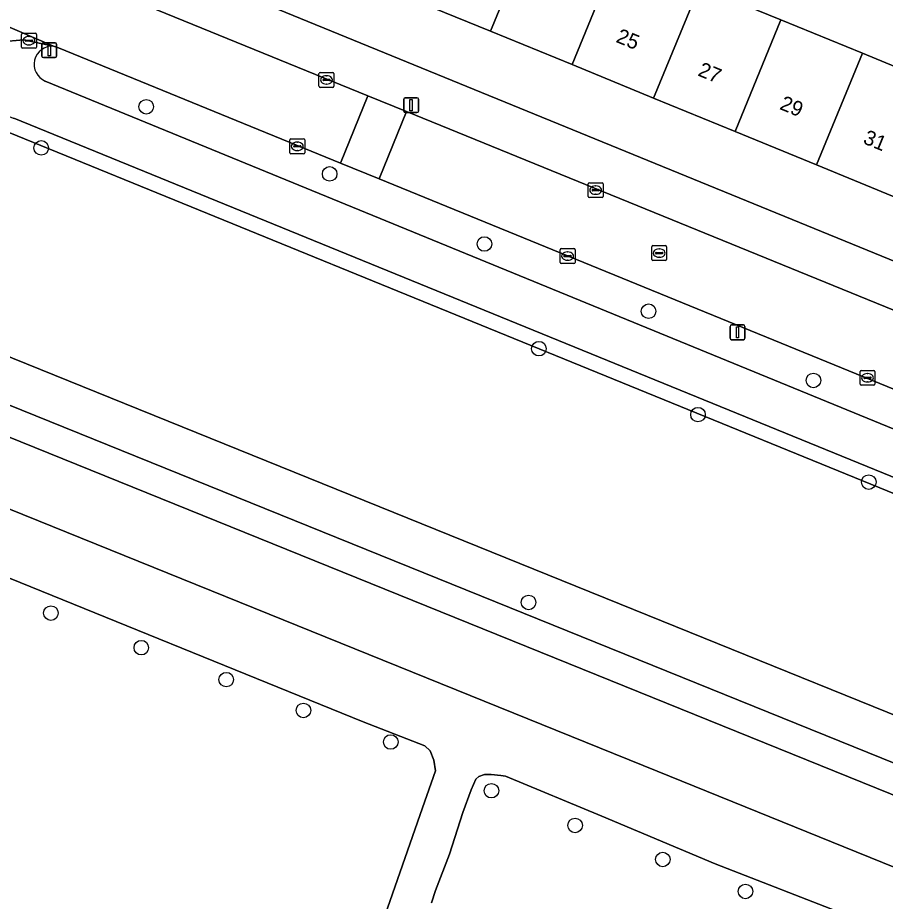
# Model space of a CAD drawing. Extents: x 163008 to 163854, y 382777 to 383982.
# Drawn here: x 163552.6 to 163610.9, y 383061.9 to 383121.3 of the extents above; entities that cross this region are included whole.
import ezdxf

# ---------------------------------------------------------------- set-up
doc = ezdxf.new("R2010")
doc.units = 0
for name, color, linetype in [('IMGEO_Berm_groen', 7, 'Continuous'), ('IMGEO_Boom', 7, 'Continuous'), ('IMGEO_Erf', 7, 'Continuous'), ('IMGEO_Groenvoorziening', 7, 'Continuous'), ('IMGEO_Hek', 7, 'Continuous'), ('IMGEO_Kolk', 7, 'Continuous'), ('IMGEO_Lichtmast', 7, 'Continuous'), ('IMGEO_Pand', 7, 'Continuous'), ('IMGEO_Pand_nummerreeks', 7, 'Continuous'), ('IMGEO_Parkeervlak_open', 7, 'Continuous'), ('IMGEO_Rijbaan_lokaal_open', 7, 'Continuous'), ('IMGEO_Rioolput', 7, 'Continuous'), ('IMGEO_Voetpad_gesloten', 7, 'Continuous'), ('IMGEO_Voetpad_open', 7, 'Continuous')]:
    doc.layers.add(name, color=color, linetype=linetype)

msp = doc.modelspace()

# ---------------------------------------------------------------- linework, layer by layer
at = {"layer": 'IMGEO_Berm_groen'}
for points in [[(163633.015, 383087.498), (163631.359, 383088.175), (163576.844, 383110.459), (163574.252, 383111.519), (163555.314, 383119.26), (163554.966, 383119.373)], [(163554.417, 383117.031), (163686.887, 383062.727), (163714.179, 383051.656), (163715.856, 383050.902), (163716.385, 383050.818), (163716.76, 383053.267), (163697.913, 383060.965), (163695.331, 383062.02), (163685.312, 383066.121), (163633.015, 383087.498)]]:
    msp.add_lwpolyline(points, dxfattribs=at)
msp.add_arc((163554.875, 383118.159), 1.217, 85.72672, 247.88771, dxfattribs=at)
at = {"layer": 'IMGEO_Boom'}
for centre in [(163561.196, 383115.303), (163554.141, 383112.541), (163573.523, 383110.796), (163583.92, 383106.088), (163594.951, 383101.57), (163587.584, 383099.053), (163606.03, 383096.921), (163598.27, 383094.624), (163609.743, 383090.094), (163586.888, 383082.01), (163554.791, 383081.29), (163560.866, 383078.968), (163566.573, 383076.823), (163571.758, 383074.753), (163577.63, 383072.633), (163584.393, 383069.36), (163590.011, 383067.025), (163595.908, 383064.74), (163601.462, 383062.595)]:
    msp.add_circle(centre, 0.489, dxfattribs=at)
at = {"layer": 'IMGEO_Erf'}
for points in [[(163611.721, 383109.153), (163606.243, 383111.398), (163600.766, 383113.643), (163595.287, 383115.889), (163589.811, 383118.134), (163584.332, 383120.38), (163578.855, 383122.625), (163573.377, 383124.871), (163567.9, 383127.116), (163562.422, 383129.362), (163556.757, 383131.684), (163555.276, 383128.633), (163555.2, 383128.339), (163555.351, 383127.886), (163648.196, 383089.907)], [(163598.363, 383123.391), (163603.841, 383121.145), (163609.319, 383118.9), (163614.796, 383116.655)]]:
    msp.add_lwpolyline(points, dxfattribs=at)
at = {"layer": 'IMGEO_Groenvoorziening'}
for points in [[(163716.496, 383040.091), (163717.253, 383045.653), (163715.928, 383047.135), (163714.893, 383048.292), (163712.787, 383049.042), (163686.049, 383059.953), (163684.533, 383060.571), (163683.641, 383060.935), (163682.71, 383061.315), (163552.303, 383114.53)], [(163548.402, 383113.844), (163537.893, 383104.199), (163535.444, 383101.951), (163672.395, 383046.546)], [(163715.519, 383040.306), (163716.256, 383044.834), (163714.021, 383047.565), (163682.332, 383060.389), (163551.925, 383113.604)], [(163551.925, 383113.604), (163682.332, 383060.389), (163714.021, 383047.565), (163716.256, 383044.834), (163715.519, 383040.306)], [(163549.078, 383113.107), (163538.918, 383103.782), (163673.52, 383049.327)], [(163673.52, 383049.327), (163538.918, 383103.782)], [(163535.444, 383101.951), (163533.814, 383100.455), (163671.636, 383044.697), (163673.119, 383044.03), (163675.855, 383042.527), (163676.469, 383042.1), (163678.419, 383040.746), (163680.783, 383038.707), (163682.026, 383037.276), (163683.551, 383038.568), (163682.233, 383040.085)], [(163672.395, 383046.546), (163535.444, 383101.951)], [(163671.636, 383044.697), (163533.814, 383100.455)], [(163547.123, 383090.252), (163595.525, 383070.679), (163613.979, 383063.189)], [(163608.409, 383060.95), (163599.416, 383064.447), (163591.815, 383067.641), (163585.343, 383070.338), (163585.029, 383070.374), (163584.368, 383070.447), (163583.933, 383070.447), (163583.54, 383070.317), (163583.353, 383070.144), (163583.039, 383069.427), (163582.464, 383067.89), (163581.572, 383065.105), (163580.642, 383062.658), (163580.364, 383061.824)]]:
    msp.add_lwpolyline(points, dxfattribs=at)
msp.add_lwpolyline([(163547.02, 383081.384), (163546.673, 383080.294), (163540.33, 383061.689), (163539.081, 383058.231), (163572.325, 383046.79), (163572.711, 383047.998), (163579.758, 383068.217), (163580.638, 383070.701), (163580.512, 383071.408), (163580.28, 383072.028), (163579.921, 383072.377), (163575.785, 383073.992), (163549.831, 383084.522), (163549.324, 383084.673), (163548.823, 383084.551), (163548.394, 383084.316), (163548.147, 383084.045), (163547.849, 383083.514)], close=True, dxfattribs=at)
at = {"layer": 'IMGEO_Hek'}
msp.add_lwpolyline([(163533.814, 383100.455), (163671.636, 383044.697), (163673.119, 383044.03), (163675.855, 383042.527), (163676.469, 383042.1)], dxfattribs=at)
at = {"layer": 'IMGEO_Kolk'}
for p, q in [((163552.816, 383119.318), (163552.816, 383120.17)), ((163552.891, 383120.244), (163553.743, 383120.244)), ((163553.304, 383120.024), (163553.329, 383120.024)), ((163553.817, 383120.17), (163553.817, 383119.318)), ((163553.075, 383119.738), (163553.075, 383119.75)), ((163553.513, 383119.701), (163553.115, 383119.701)), ((163553.118, 383119.787), (163553.516, 383119.787)), ((163553.327, 383119.464), (163553.302, 383119.464)), ((163553.559, 383119.75), (163553.559, 383119.738)), ((163553.743, 383119.244), (163552.891, 383119.244)), ((163572.806, 383116.683), (163572.806, 383117.535)), ((163572.881, 383117.609), (163573.733, 383117.609)), ((163573.807, 383117.535), (163573.807, 383116.683)), ((163573.065, 383117.103), (163573.065, 383117.115)), ((163573.503, 383117.066), (163573.105, 383117.066)), ((163573.108, 383117.152), (163573.506, 383117.152)), ((163573.294, 383117.389), (163573.319, 383117.389)), ((163573.549, 383117.115), (163573.549, 383117.103)), ((163573.733, 383116.609), (163572.881, 383116.609)), ((163573.317, 383116.829), (163573.292, 383116.829)), ((163570.847, 383112.221), (163570.847, 383113.073)), ((163570.922, 383113.147), (163571.774, 383113.147)), ((163571.335, 383112.927), (163571.36, 383112.927)), ((163571.848, 383113.073), (163571.848, 383112.221)), ((163571.774, 383112.147), (163570.922, 383112.147)), ((163571.106, 383112.641), (163571.106, 383112.653)), ((163571.544, 383112.604), (163571.146, 383112.604)), ((163571.149, 383112.69), (163571.547, 383112.69)), ((163571.358, 383112.367), (163571.333, 383112.367)), ((163571.59, 383112.653), (163571.59, 383112.641)), ((163590.896, 383109.277), (163590.896, 383110.129)), ((163590.971, 383110.203), (163591.823, 383110.203)), ((163591.384, 383109.983), (163591.409, 383109.983)), ((163591.897, 383110.129), (163591.897, 383109.277)), ((163591.823, 383109.203), (163590.971, 383109.203)), ((163591.155, 383109.697), (163591.155, 383109.709)), ((163591.593, 383109.66), (163591.195, 383109.66)), ((163591.198, 383109.746), (163591.596, 383109.746)), ((163591.407, 383109.423), (163591.382, 383109.423)), ((163591.639, 383109.709), (163591.639, 383109.697)), ((163589.008, 383104.85), (163589.008, 383105.702)), ((163589.083, 383105.776), (163589.935, 383105.776)), ((163590.009, 383105.702), (163590.009, 383104.85)), ((163589.267, 383105.27), (163589.267, 383105.282)), ((163589.705, 383105.233), (163589.307, 383105.233)), ((163589.31, 383105.319), (163589.708, 383105.319)), ((163589.496, 383105.556), (163589.521, 383105.556)), ((163589.751, 383105.282), (163589.751, 383105.27)), ((163589.935, 383104.776), (163589.083, 383104.776)), ((163589.519, 383104.996), (163589.494, 383104.996)), ((163609.16, 383096.67), (163609.16, 383097.522)), ((163609.235, 383097.596), (163610.087, 383097.596)), ((163609.648, 383097.376), (163609.673, 383097.376)), ((163610.161, 383097.522), (163610.161, 383096.67)), ((163609.419, 383097.09), (163609.419, 383097.102)), ((163609.857, 383097.053), (163609.459, 383097.053)), ((163609.462, 383097.139), (163609.86, 383097.139)), ((163609.671, 383096.816), (163609.646, 383096.816)), ((163609.903, 383097.102), (163609.903, 383097.09)), ((163610.087, 383096.596), (163609.235, 383096.596))]:
    msp.add_line(p, q, dxfattribs=at)
for points in [[(163552.816, 383119.318), (163552.816, 383120.17)], [(163552.891, 383120.244), (163553.743, 383120.244)], [(163553.817, 383120.17), (163553.817, 383119.318)], [(163553.743, 383119.244), (163552.891, 383119.244)], [(163572.806, 383116.683), (163572.806, 383117.535)], [(163572.881, 383117.609), (163573.733, 383117.609)], [(163573.807, 383117.535), (163573.807, 383116.683)], [(163573.733, 383116.609), (163572.881, 383116.609)], [(163570.847, 383112.221), (163570.847, 383113.073)], [(163570.922, 383113.147), (163571.774, 383113.147)], [(163571.848, 383113.073), (163571.848, 383112.221)], [(163571.774, 383112.147), (163570.922, 383112.147)], [(163590.896, 383109.277), (163590.896, 383110.129)], [(163590.971, 383110.203), (163591.823, 383110.203)], [(163591.897, 383110.129), (163591.897, 383109.277)], [(163591.823, 383109.203), (163590.971, 383109.203)], [(163589.008, 383104.85), (163589.008, 383105.702)], [(163589.083, 383105.776), (163589.935, 383105.776)], [(163590.009, 383105.702), (163590.009, 383104.85)], [(163589.935, 383104.776), (163589.083, 383104.776)], [(163609.16, 383096.67), (163609.16, 383097.522)], [(163609.235, 383097.596), (163610.087, 383097.596)], [(163610.161, 383097.522), (163610.161, 383096.67)], [(163610.087, 383096.596), (163609.235, 383096.596)]]:
    msp.add_lwpolyline(points, dxfattribs=at)
for centre, radius, start, end in [((163552.893, 383120.168), 0.0765, 91.55205, 178.44795), ((163552.893, 383120.168), 0.0765, 91.55205, 178.44795), ((163553.741, 383120.168), 0.0765, 1.55205, 88.44795), ((163553.741, 383120.168), 0.0765, 1.55205, 88.44795), ((163552.893, 383119.32), 0.0765, 181.55205, 268.44795), ((163552.893, 383119.32), 0.0765, 181.55205, 268.44795), ((163553.115, 383119.747), 0.0403, 85.87752, 175.75265), ((163553.112, 383119.737), 0.0366, 178.93798, 274.71019), ((163553.516, 383119.744), 0.043, 264.86636, 352.45326), ((163553.52, 383119.749), 0.0386, 1.73085, 96.63898), ((163553.741, 383119.32), 0.0765, 271.55205, 358.44795), ((163553.741, 383119.32), 0.0765, 271.55205, 358.44795), ((163572.883, 383117.533), 0.0765, 91.55205, 178.44795), ((163572.883, 383117.533), 0.0765, 91.55205, 178.44795), ((163573.731, 383117.533), 0.0765, 1.55205, 88.44795), ((163573.731, 383117.533), 0.0765, 1.55205, 88.44795), ((163573.105, 383117.112), 0.0403, 85.87752, 175.75265), ((163573.102, 383117.102), 0.0366, 178.93798, 274.71019), ((163573.506, 383117.109), 0.043, 264.86636, 352.45326), ((163573.51, 383117.114), 0.0386, 1.73085, 96.63898), ((163572.883, 383116.685), 0.0765, 181.55205, 268.44795), ((163572.883, 383116.685), 0.0765, 181.55205, 268.44795), ((163573.731, 383116.685), 0.0765, 271.55205, 358.44795), ((163573.731, 383116.685), 0.0765, 271.55205, 358.44795), ((163570.924, 383113.071), 0.0765, 91.55205, 178.44795), ((163570.924, 383113.071), 0.0765, 91.55205, 178.44795), ((163571.772, 383113.071), 0.0765, 1.55205, 88.44795), ((163571.772, 383113.071), 0.0765, 1.55205, 88.44795), ((163570.924, 383112.223), 0.0765, 181.55205, 268.44795), ((163570.924, 383112.223), 0.0765, 181.55205, 268.44795), ((163571.146, 383112.65), 0.0403, 85.87752, 175.75265), ((163571.143, 383112.64), 0.0366, 178.93798, 274.71019), ((163571.547, 383112.647), 0.043, 264.86636, 352.45326), ((163571.551, 383112.652), 0.0386, 1.73085, 96.63898), ((163571.772, 383112.223), 0.0765, 271.55205, 358.44795), ((163571.772, 383112.223), 0.0765, 271.55205, 358.44795), ((163590.973, 383110.127), 0.0765, 91.55205, 178.44795), ((163590.973, 383110.127), 0.0765, 91.55205, 178.44795), ((163591.821, 383110.127), 0.0765, 1.55205, 88.44795), ((163591.821, 383110.127), 0.0765, 1.55205, 88.44795), ((163590.973, 383109.279), 0.0765, 181.55205, 268.44795), ((163590.973, 383109.279), 0.0765, 181.55205, 268.44795), ((163591.195, 383109.706), 0.0403, 85.87752, 175.75265), ((163591.192, 383109.696), 0.0366, 178.93798, 274.71019), ((163591.596, 383109.703), 0.043, 264.86636, 352.45326), ((163591.6, 383109.708), 0.0386, 1.73085, 96.63898), ((163591.821, 383109.279), 0.0765, 271.55205, 358.44795), ((163591.821, 383109.279), 0.0765, 271.55205, 358.44795), ((163589.085, 383105.7), 0.0765, 91.55205, 178.44795), ((163589.085, 383105.7), 0.0765, 91.55205, 178.44795), ((163589.933, 383105.7), 0.0765, 1.55205, 88.44795), ((163589.933, 383105.7), 0.0765, 1.55205, 88.44795), ((163589.307, 383105.279), 0.0403, 85.87752, 175.75265), ((163589.304, 383105.269), 0.0366, 178.93798, 274.71019), ((163589.708, 383105.276), 0.043, 264.86636, 352.45326), ((163589.712, 383105.281), 0.0386, 1.73085, 96.63898), ((163589.085, 383104.852), 0.0765, 181.55205, 268.44795), ((163589.085, 383104.852), 0.0765, 181.55205, 268.44795), ((163589.933, 383104.852), 0.0765, 271.55205, 358.44795), ((163589.933, 383104.852), 0.0765, 271.55205, 358.44795), ((163609.237, 383097.52), 0.0765, 91.55205, 178.44795), ((163609.237, 383097.52), 0.0765, 91.55205, 178.44795), ((163610.085, 383097.52), 0.0765, 1.55205, 88.44795), ((163610.085, 383097.52), 0.0765, 1.55205, 88.44795), ((163609.459, 383097.099), 0.0403, 85.87752, 175.75265), ((163609.456, 383097.089), 0.0366, 178.93798, 274.71019), ((163609.86, 383097.096), 0.043, 264.86636, 352.45326), ((163609.864, 383097.101), 0.0386, 1.73085, 96.63898), ((163609.237, 383096.672), 0.0765, 181.55205, 268.44795), ((163609.237, 383096.672), 0.0765, 181.55205, 268.44795), ((163610.085, 383096.672), 0.0765, 271.55205, 358.44795), ((163610.085, 383096.672), 0.0765, 271.55205, 358.44795)]:
    msp.add_arc(centre, radius, start, end, dxfattribs=at)
for centre, major_axis, ratio, start_param, end_param in [((163553.303, 383119.744), (-0.387, 0.002), 0.722429, 4.712389, 7.853982), ((163553.328, 383119.744), (-0.39, 0.002), 0.717154, 1.570796, 4.712389), ((163573.293, 383117.109), (-0.387, 0.002), 0.722429, 4.712389, 7.853982), ((163573.318, 383117.109), (-0.39, 0.002), 0.717154, 1.570796, 4.712389), ((163571.334, 383112.647), (-0.387, 0.002), 0.722429, 4.712389, 7.853982), ((163571.359, 383112.647), (-0.39, 0.002), 0.717154, 1.570796, 4.712389), ((163591.383, 383109.703), (-0.387, 0.002), 0.722429, 4.712389, 7.853982), ((163591.408, 383109.703), (-0.39, 0.002), 0.717154, 1.570796, 4.712389), ((163589.495, 383105.276), (-0.387, 0.002), 0.722429, 4.712389, 7.853982), ((163589.52, 383105.276), (-0.39, 0.002), 0.717154, 1.570796, 4.712389), ((163609.647, 383097.096), (-0.387, 0.002), 0.722429, 4.712389, 7.853982), ((163609.672, 383097.096), (-0.39, 0.002), 0.717154, 1.570796, 4.712389)]:
    msp.add_ellipse(centre, major_axis=major_axis, ratio=ratio, start_param=start_param, end_param=end_param, dxfattribs=at)
at = {"layer": 'IMGEO_Lichtmast'}
for p, q in [((163554.186, 383118.706), (163554.186, 383119.506)), ((163554.186, 383119.506), (163554.186, 383118.706)), ((163554.286, 383119.606), (163555.076, 383119.606)), ((163555.076, 383119.606), (163554.286, 383119.606)), ((163555.176, 383119.506), (163555.176, 383118.706)), ((163555.176, 383118.706), (163555.176, 383119.506)), ((163555.076, 383118.606), (163554.286, 383118.606)), ((163554.286, 383118.606), (163555.076, 383118.606)), ((163578.5, 383115.014), (163578.5, 383115.814)), ((163578.5, 383115.814), (163578.5, 383115.014)), ((163578.6, 383115.914), (163579.39, 383115.914)), ((163579.39, 383115.914), (163578.6, 383115.914)), ((163579.49, 383115.814), (163579.49, 383115.014)), ((163579.49, 383115.014), (163579.49, 383115.814)), ((163579.39, 383114.914), (163578.6, 383114.914)), ((163578.6, 383114.914), (163579.39, 383114.914)), ((163600.432, 383099.755), (163600.432, 383100.555)), ((163600.432, 383100.555), (163600.432, 383099.755)), ((163600.532, 383100.655), (163601.322, 383100.655)), ((163601.322, 383100.655), (163600.532, 383100.655)), ((163601.422, 383100.555), (163601.422, 383099.755)), ((163601.422, 383099.755), (163601.422, 383100.555)), ((163601.322, 383099.655), (163600.532, 383099.655)), ((163600.532, 383099.655), (163601.322, 383099.655))]:
    msp.add_line(p, q, dxfattribs=at)
for points in [[(163554.606, 383119.481), (163554.756, 383119.481), (163554.756, 383118.731), (163554.606, 383118.731), (163554.606, 383119.481)], [(163578.92, 383115.789), (163579.07, 383115.789), (163579.07, 383115.039), (163578.92, 383115.039), (163578.92, 383115.789)], [(163600.852, 383100.53), (163601.002, 383100.53), (163601.002, 383099.78), (163600.852, 383099.78), (163600.852, 383100.53)]]:
    msp.add_lwpolyline(points, dxfattribs=at)
for centre, start, end in [((163554.286, 383119.506), 90, 180), ((163554.286, 383119.506), 90, 180), ((163555.076, 383119.506), 0, 90), ((163555.076, 383119.506), 360, 90), ((163554.286, 383118.706), 180, 270), ((163554.286, 383118.706), 180, 270), ((163555.076, 383118.706), 270, 0), ((163555.076, 383118.706), 270, 0), ((163578.6, 383115.814), 90, 180), ((163578.6, 383115.814), 90, 180), ((163579.39, 383115.814), 0, 90), ((163579.39, 383115.814), 360, 90), ((163578.6, 383115.014), 180, 270), ((163578.6, 383115.014), 180, 270), ((163579.39, 383115.014), 270, 0), ((163579.39, 383115.014), 270, 0), ((163600.532, 383100.555), 90, 180), ((163600.532, 383100.555), 90, 180), ((163601.322, 383100.555), 0, 90), ((163601.322, 383100.555), 360, 90), ((163600.532, 383099.755), 180, 270), ((163600.532, 383099.755), 180, 270), ((163601.322, 383099.755), 270, 0), ((163601.322, 383099.755), 270, 0)]:
    msp.add_arc(centre, 0.1, start, end, dxfattribs=at)
at = {"layer": 'IMGEO_Pand'}
for points in [[(163587.412, 383127.893), (163588.468, 383130.468), (163584.459, 383132.11), (163582.99, 383132.712), (163581.928, 383130.12), (163578.855, 383122.625), (163584.332, 383120.38)], [(163584.332, 383120.38), (163589.811, 383118.134), (163592.89, 383125.648), (163587.412, 383127.893)], [(163598.363, 383123.391), (163595.582, 383124.531), (163592.89, 383125.648), (163589.811, 383118.134), (163595.287, 383115.889)], [(163598.363, 383123.391), (163595.287, 383115.889), (163600.766, 383113.643), (163603.841, 383121.145)], [(163609.319, 383118.9), (163603.841, 383121.145), (163600.766, 383113.643), (163606.243, 383111.398)], [(163611.721, 383109.153), (163614.796, 383116.655), (163609.319, 383118.9), (163606.243, 383111.398)]]:
    msp.add_lwpolyline(points, close=True, dxfattribs=at)
at = {"layer": 'IMGEO_Parkeervlak_open'}
msp.add_lwpolyline([(163547.165, 383116.627), (163550.032, 383119.196), (163551.454, 383119.671), (163552.953, 383119.796), (163554.966, 383119.373), (163547.625, 383122.548), (163543.777, 383123.82)], dxfattribs=at)
at = {"layer": 'IMGEO_Rijbaan_lokaal_open'}
msp.add_lwpolyline([(163543.777, 383123.82), (163547.625, 383122.548), (163554.966, 383119.373), (163555.314, 383119.26), (163574.252, 383111.519), (163576.095, 383116.039), (163550.724, 383126.385), (163547.235, 383127.815), (163537.399, 383131.89)], dxfattribs=at)
for points in [[(163574.252, 383111.519), (163576.844, 383110.459), (163578.688, 383114.981), (163576.095, 383116.039)], [(163631.359, 383088.175), (163633.221, 383092.742), (163578.688, 383114.981), (163576.844, 383110.459)]]:
    msp.add_lwpolyline(points, close=True, dxfattribs=at)
at = {"layer": 'IMGEO_Rioolput'}
for p, q in [((163595.163, 383105.052), (163595.163, 383105.904)), ((163595.238, 383105.978), (163596.09, 383105.978)), ((163595.651, 383105.758), (163595.676, 383105.758)), ((163596.164, 383105.904), (163596.164, 383105.052)), ((163595.422, 383105.472), (163595.422, 383105.484)), ((163595.86, 383105.435), (163595.462, 383105.435)), ((163595.465, 383105.521), (163595.863, 383105.521)), ((163595.674, 383105.198), (163595.649, 383105.198)), ((163595.906, 383105.484), (163595.906, 383105.472)), ((163596.09, 383104.978), (163595.238, 383104.978))]:
    msp.add_line(p, q, dxfattribs=at)
for points in [[(163595.163, 383105.052), (163595.163, 383105.904)], [(163595.238, 383105.978), (163596.09, 383105.978)], [(163596.164, 383105.904), (163596.164, 383105.052)], [(163596.09, 383104.978), (163595.238, 383104.978)]]:
    msp.add_lwpolyline(points, dxfattribs=at)
for centre, radius, start, end in [((163595.24, 383105.902), 0.0765, 91.55205, 178.44795), ((163595.24, 383105.902), 0.0765, 91.55205, 178.44795), ((163596.088, 383105.902), 0.0765, 1.55205, 88.44795), ((163596.088, 383105.902), 0.0765, 1.55205, 88.44795), ((163595.24, 383105.054), 0.0765, 181.55205, 268.44795), ((163595.24, 383105.054), 0.0765, 181.55205, 268.44795), ((163595.462, 383105.481), 0.0403, 85.87752, 175.75265), ((163595.459, 383105.471), 0.0366, 178.93798, 274.71019), ((163595.863, 383105.478), 0.043, 264.86636, 352.45326), ((163595.867, 383105.483), 0.0386, 1.73085, 96.63898), ((163596.088, 383105.054), 0.0765, 271.55205, 358.44795), ((163596.088, 383105.054), 0.0765, 271.55205, 358.44795)]:
    msp.add_arc(centre, radius, start, end, dxfattribs=at)
for centre, major_axis, ratio, start_param, end_param in [((163595.65, 383105.478), (-0.387, 0.002), 0.722429, 4.712389, 7.853982), ((163595.675, 383105.478), (-0.39, 0.002), 0.717154, 1.570796, 4.712389)]:
    msp.add_ellipse(centre, major_axis=major_axis, ratio=ratio, start_param=start_param, end_param=end_param, dxfattribs=at)
at = {"layer": 'IMGEO_Voetpad_gesloten'}
for points in [[(163613.979, 383063.189), (163595.525, 383070.679), (163547.123, 383090.252)], [(163540.33, 383061.689), (163546.673, 383080.294), (163547.02, 383081.384), (163547.849, 383083.514), (163548.147, 383084.045), (163548.394, 383084.316), (163548.823, 383084.551), (163549.324, 383084.673), (163549.831, 383084.522), (163575.785, 383073.992), (163579.921, 383072.377), (163580.28, 383072.028), (163580.512, 383071.408), (163580.638, 383070.701), (163579.758, 383068.217), (163572.711, 383047.998)], [(163580.364, 383061.824), (163580.642, 383062.658), (163581.572, 383065.105), (163582.464, 383067.89), (163583.039, 383069.427), (163583.353, 383070.144), (163583.54, 383070.317), (163583.933, 383070.447), (163584.368, 383070.447), (163585.029, 383070.374), (163585.343, 383070.338), (163591.815, 383067.641), (163599.416, 383064.447), (163608.409, 383060.95)]]:
    msp.add_lwpolyline(points, dxfattribs=at)
at = {"layer": 'IMGEO_Voetpad_open'}
for points in [[(163713.136, 383063.343), (163650.485, 383088.971), (163650.083, 383089.135), (163648.196, 383089.907), (163555.351, 383127.886), (163554.767, 383128.125), (163553.968, 383128.582), (163551.599, 383129.553), (163538.257, 383135.219)], [(163537.399, 383131.89), (163547.235, 383127.815), (163547.424, 383128.277), (163550.913, 383126.847), (163550.724, 383126.385), (163576.095, 383116.039), (163578.688, 383114.981), (163633.221, 383092.742), (163634.878, 383092.067), (163697.216, 383066.645), (163699.799, 383065.591), (163711.825, 383060.619), (163713.699, 383059.861), (163714.336, 383064.187)], [(163554.966, 383119.373), (163552.953, 383119.796), (163551.454, 383119.671), (163550.032, 383119.196), (163547.165, 383116.627), (163552.254, 383114.55), (163552.303, 383114.53), (163682.71, 383061.315), (163683.641, 383060.935), (163684.533, 383060.571), (163686.049, 383059.953), (163712.787, 383049.042), (163714.893, 383048.292), (163715.928, 383047.135), (163716.385, 383050.818), (163715.856, 383050.902), (163714.179, 383051.656), (163686.887, 383062.727)], [(163686.887, 383062.727), (163554.417, 383117.031)]]:
    msp.add_lwpolyline(points, dxfattribs=at)
msp.add_arc((163554.875, 383118.159), 1.217, 85.72672, 247.88771, dxfattribs=at)

# ---------------------------------------------------------------- texts
at = {"layer": 'IMGEO_Pand_nummerreeks'}
for s, rotation, p in [('25', 337.71194, (163592.698, 383119.673)), ('27', 337.70983, (163598.199, 383117.419)), ('29', 337.70983, (163603.698, 383115.164)), ('31', 337.70983, (163609.302, 383112.868))]:
    msp.add_text(s, height=1, rotation=rotation, dxfattribs=at).set_placement(p)

doc.saveas('drawing.dxf')
